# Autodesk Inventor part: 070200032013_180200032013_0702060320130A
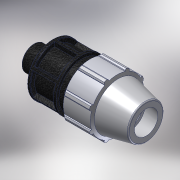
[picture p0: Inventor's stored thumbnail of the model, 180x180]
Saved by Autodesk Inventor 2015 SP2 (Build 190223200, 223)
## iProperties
Created: 2017-02
Part Number: 070200032013_180200032013_0702060320130A
Material: PVC-Piping
Description: PLASSON MALE ADAPTOR 32-1.1/4"
Document SubType Name: Modeling
Designer: KIM
Mass: 92.6774 g
Surface Area: 199.44 cm^2
Volume: 66.1981 cm^3
Density: 1.4 g/cm^3
Appearance: PTFE
Author: KIM
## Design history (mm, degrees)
derived "07020.ipt"
feature "Solid1::07020.ipt"
tag "TaggingFeature1"
body "Solid1"
other parameters: "d2" = 32, "d4" = 15.71429, "d5" = 27.5, "d7" = 64, "d8" = 48, "d9" = 15.71429, "d11" = 3.14286, "d12" = 51.2, "d13" = 120 deg, "d14" = 48, "d15" = 10 deg, "d16" = 57.6, "d18" = 1.6, "d19" = 35 deg, "d20" = 17.5 deg, "d21" = 59.52, "d23" = 0, "d25" = 360 deg, "d27" = 1.28, "d34" = 3.2, "d36" = 0, "d42" = 27.5, "d43" = 1.92, "d46" = 0.96, "d49" = 83, "d52" = 22, "d53" = 0.64, "d55" = 360 deg, "d57" = 41.91, "d58" = 29.337, "d59" = 22, "d_" = 32, "E_" = 64, "l_" = 83, "l_2" = 22, "R_" = 41.91
